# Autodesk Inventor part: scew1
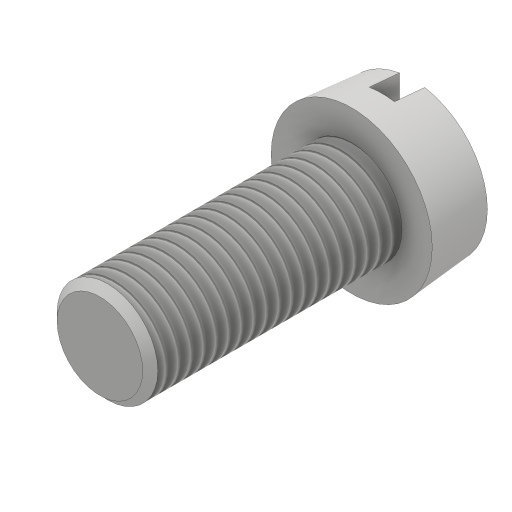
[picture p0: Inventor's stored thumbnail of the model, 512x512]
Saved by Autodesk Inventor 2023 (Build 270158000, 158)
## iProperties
Created: 2016-05
Part Number: scew1
Material: Generic
Document SubType Name: Modeling
Designer: CADCIM
Density: 1 g/cm^3
Appearance: Default
Author: CADCIM
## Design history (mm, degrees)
sketch "Sketch1"
  geometry: C1 r 9.6 at (0, 0); 1 further point
  constraints: 1 centre point, 1 coincident
  dimensions: "d0" = 19.2 diameter of C1
extrude "Extrusion1" new body sketch "Sketch1" distance "d1" = 7.2; taper "d2" = -5 deg
sketch "Sketch3"
  geometry: C1 r 6 at (0, 0); 1 further point
  constraints: 1 centre point, 1 coincident
  dimensions: "d7" = 12 diameter of C1
extrude "Extrusion3" join sketch "Sketch3" distance "d8" = 30; taper "d9" = 0 deg
thread "Thread1" dims "d13" = 10, "d14" = 0
chamfer "Chamfer2" distance "d15" = 0.9; stored, may be unused: second distance "d16" = 2, angle "d17" = 45 deg
sketch "Sketch4"
  geometry: L1 (1.5, -10.35)-(-1.5, -10.35); L2 (-1.5, -10.35)-(-1.5, 10.35); L3 (-1.5, 10.35)-(1.5, 10.35); L4 (1.5, 10.35)-(1.5, -10.35); L5 (0, -10.35)-(0, 10.35); 2 further points
  constraints: 10 end point, 3 midpoint, 2 parallel, 1 coincident, 1 horizontal, 1 perpendicular
  dimensions: "d18" = 3 distance of L1.start L1.end
extrude "Extrusion4" cut sketch "Sketch4" distance "d19" = 3.6; taper "d20" = 0 deg
body "Solid1"
